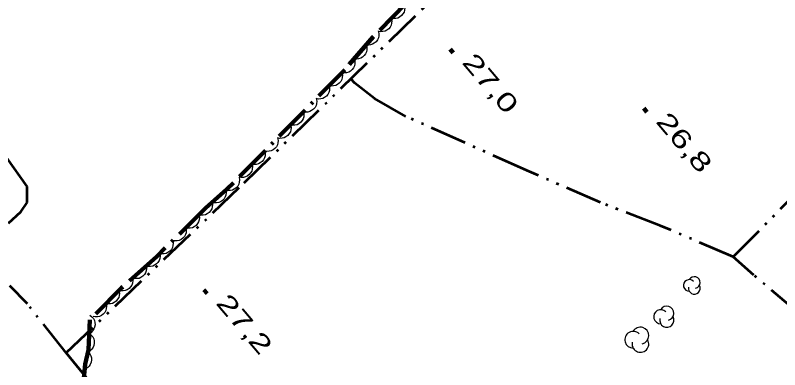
# Model space of a CAD drawing. Extents: x 386081 to 389416, y 5130568 to 5134082.
# Drawn here: x 388146 to 388270.9, y 5131665.7 to 5131723.7 of the extents above; entities that cross this region are included whole.
import ezdxf

# ---------------------------------------------------------------- set-up
doc = ezdxf.new("R2010")
doc.units = 0
doc.header["$LTSCALE"] = 1.2
doc.linetypes.add('DASH_DOUBLE_DOT', pattern=[9.2, 5, -1.2, 0.3, -1.2, 0.3, -1.2])
doc.linetypes.add('DOT_DASHED', pattern=[7.7, 5, -1.2, 0.3, -1.2])
for name, color, linetype, lineweight in [('3', 7, 'Continuous', 140), ('4', 7, 'DASH_DOUBLE_DOT', 53), ('44', 7, 'Continuous', 25)]:
    doc.layers.add(name, color=color, linetype=linetype, lineweight=lineweight)

msp = doc.modelspace()

# ---------------------------------------------------------------- linework, layer by layer
at = {"layer": '3'}
for p, q in [((388217.02, 5131718.17), (388217.53, 5131717.56)), ((388248.67, 5131708.5), (388249.18, 5131707.89)), ((388176.81, 5131678.8), (388177.32, 5131678.19))]:
    msp.add_line(p, q, dxfattribs=at)
at = {"layer": '4'}
for points in [[(388204.21, 5131610.66), (388196.86, 5131620.2), (388175.99, 5131644.63), (388165.41, 5131656.62), (388157.68, 5131664.34), (388154.31, 5131668.51), (388183.39, 5131696.3), (388212.47, 5131724.71), (388239.36, 5131750.62), (388265.61, 5131776.18), (388295.56, 5131805.65), (388308.21, 5131817.54), (388331.7, 5131840.05), (388348.88, 5131856.91), (388363.69, 5131871.25), (388382.99, 5131889.58), (388381.01, 5131890.93)], [(388263.29, 5131684.19), (388275.69, 5131696.8), (388295.26, 5131716.36), (388314.97, 5131735.57), (388331.43, 5131751.08), (388342.34, 5131761.72), (388346.88, 5131765.95), (388336.97, 5131780.58), (388318.64, 5131804.44), (388312.82, 5131811.58), (388308.21, 5131817.54)], [(388282.9, 5131667.63), (388274.12, 5131674.87), (388266.63, 5131681.22), (388263.29, 5131684.19), (388251.41, 5131689.3), (388241.59, 5131693.09), (388229.55, 5131698.34), (388209.82, 5131707.18), (388204.66, 5131710.12), (388201.44, 5131712.61), (388200.82, 5131713.34)], [(388144.86, 5131689.71), (388146.88, 5131691.59), (388147.91, 5131693.09), (388147.91, 5131695.74), (388144.6, 5131700.38)], [(388154.32, 5131668.51), (388147.98, 5131676.51), (388145.09, 5131679.45)]]:
    msp.add_lwpolyline(points, dxfattribs=at)
at = {"layer": '44', "linetype": 'DOT_DASHED', "lineweight": 90}
msp.add_lwpolyline([(388275.17, 5131788.24), (388266.86, 5131779.86), (388261.37, 5131774.72), (388253.26, 5131766.73), (388250.48, 5131764.17), (388246.51, 5131760.34), (388243.72, 5131757.88), (388240.74, 5131755.43), (388237.73, 5131752.74), (388224.13, 5131739.09), (388216.64, 5131732.25), (388209.73, 5131725.59), (388204.46, 5131720.2), (388199.81, 5131714.8), (388181.62, 5131696.3), (388180.56, 5131695.26), (388177.08, 5131692.16), (388169.1, 5131684.28), (388163.35, 5131679.13), (388158.15, 5131673.88), (388157.96, 5131668.98), (388157.4, 5131666.65), (388157.17, 5131664.33)], dxfattribs=at)
at = {"layer": '44'}
for points in [[(388209.53, 5131725.38), (388209.61, 5131724.97), (388209.57, 5131724.57), (388209.5, 5131724.25), (388209.33, 5131723.94), (388209.09, 5131723.66), (388208.78, 5131723.43), (388208.5, 5131723.27), (388208.16, 5131723.19), (388207.79, 5131723.17), (388207.43, 5131723.24)], [(388207.43, 5131723.24), (388207.51, 5131722.83), (388207.48, 5131722.42), (388207.4, 5131722.1), (388207.23, 5131721.8), (388207, 5131721.51), (388206.69, 5131721.29), (388206.4, 5131721.12), (388206.06, 5131721.05), (388205.69, 5131721.03), (388205.33, 5131721.09)], [(388205.28, 5131721.15), (388205.39, 5131720.74), (388205.37, 5131720.34), (388205.32, 5131720.01), (388205.17, 5131719.7), (388204.95, 5131719.4), (388204.65, 5131719.15), (388204.38, 5131718.97), (388204.04, 5131718.87), (388203.68, 5131718.83), (388203.32, 5131718.87)], [(388203.32, 5131718.87), (388203.43, 5131718.47), (388203.42, 5131718.06), (388203.36, 5131717.74), (388203.21, 5131717.42), (388202.99, 5131717.12), (388202.7, 5131716.88), (388202.43, 5131716.7), (388202.09, 5131716.6), (388201.72, 5131716.56), (388201.36, 5131716.6)], [(388201.36, 5131716.6), (388201.47, 5131716.2), (388201.46, 5131715.79), (388201.4, 5131715.46), (388201.25, 5131715.15), (388201.03, 5131714.85), (388200.74, 5131714.6), (388200.47, 5131714.42), (388200.13, 5131714.33), (388199.76, 5131714.29), (388199.4, 5131714.33)], [(388199.37, 5131714.36), (388199.46, 5131713.95), (388199.42, 5131713.54), (388199.34, 5131713.22), (388199.17, 5131712.91), (388198.93, 5131712.63), (388198.62, 5131712.4), (388198.34, 5131712.24), (388197.99, 5131712.17), (388197.62, 5131712.15), (388197.27, 5131712.22)], [(388197.27, 5131712.22), (388197.35, 5131711.81), (388197.31, 5131711.4), (388197.24, 5131711.08), (388197.06, 5131710.77), (388196.83, 5131710.49), (388196.52, 5131710.26), (388196.23, 5131710.1), (388195.89, 5131710.03), (388195.52, 5131710.01), (388195.17, 5131710.08)], [(388195.17, 5131710.08), (388195.25, 5131709.67), (388195.21, 5131709.26), (388195.13, 5131708.94), (388194.96, 5131708.64), (388194.73, 5131708.35), (388194.41, 5131708.13), (388194.13, 5131707.96), (388193.79, 5131707.89), (388193.42, 5131707.87), (388193.06, 5131707.94)], [(388193.06, 5131707.94), (388193.15, 5131707.53), (388193.11, 5131707.12), (388193.03, 5131706.8), (388192.86, 5131706.5), (388192.62, 5131706.21), (388192.31, 5131705.99), (388192.03, 5131705.82), (388191.68, 5131705.75), (388191.31, 5131705.73), (388190.96, 5131705.8)], [(388190.96, 5131705.8), (388191.04, 5131705.39), (388191, 5131704.98), (388190.93, 5131704.66), (388190.75, 5131704.36), (388190.52, 5131704.07), (388190.21, 5131703.85), (388189.92, 5131703.69), (388189.58, 5131703.61), (388189.21, 5131703.59), (388188.86, 5131703.66)], [(388188.86, 5131703.66), (388188.94, 5131703.25), (388188.9, 5131702.84), (388188.82, 5131702.52), (388188.65, 5131702.22), (388188.42, 5131701.93), (388188.1, 5131701.71), (388187.82, 5131701.55), (388187.48, 5131701.47), (388187.11, 5131701.46), (388186.75, 5131701.52)], [(388186.75, 5131701.52), (388186.84, 5131701.11), (388186.8, 5131700.71), (388186.72, 5131700.38), (388186.55, 5131700.08), (388186.31, 5131699.79), (388186, 5131699.57), (388185.72, 5131699.41), (388185.37, 5131699.33), (388185, 5131699.32), (388184.65, 5131699.38)], [(388184.65, 5131699.38), (388184.73, 5131698.97), (388184.69, 5131698.57), (388184.62, 5131698.24), (388184.44, 5131697.94), (388184.21, 5131697.65), (388183.9, 5131697.43), (388183.61, 5131697.27), (388183.27, 5131697.19), (388182.9, 5131697.18), (388182.55, 5131697.24)], [(388182.56, 5131697.22), (388182.64, 5131696.81), (388182.59, 5131696.41), (388182.51, 5131696.09), (388182.33, 5131695.79), (388182.09, 5131695.51), (388181.78, 5131695.29), (388181.49, 5131695.13), (388181.14, 5131695.06), (388180.77, 5131695.05), (388180.42, 5131695.12)], [(388180.41, 5131695.13), (388180.47, 5131694.72), (388180.4, 5131694.32), (388180.31, 5131694), (388180.11, 5131693.71), (388179.86, 5131693.44), (388179.54, 5131693.23), (388179.24, 5131693.09), (388178.89, 5131693.04), (388178.52, 5131693.05), (388178.17, 5131693.14)], [(388178.12, 5131693.19), (388178.2, 5131692.78), (388178.15, 5131692.38), (388178.08, 5131692.05), (388177.9, 5131691.75), (388177.66, 5131691.47), (388177.34, 5131691.25), (388177.06, 5131691.09), (388176.71, 5131691.02), (388176.34, 5131691.01), (388175.99, 5131691.08)], [(388175.99, 5131691.08), (388176.07, 5131690.67), (388176.02, 5131690.27), (388175.94, 5131689.95), (388175.76, 5131689.64), (388175.52, 5131689.36), (388175.21, 5131689.14), (388174.92, 5131688.98), (388174.58, 5131688.92), (388174.21, 5131688.9), (388173.85, 5131688.97)], [(388173.85, 5131688.97), (388173.93, 5131688.56), (388173.89, 5131688.16), (388173.81, 5131687.84), (388173.63, 5131687.54), (388173.39, 5131687.25), (388173.07, 5131687.03), (388172.79, 5131686.88), (388172.44, 5131686.81), (388172.07, 5131686.8), (388171.72, 5131686.87)], [(388171.72, 5131686.87), (388171.8, 5131686.46), (388171.75, 5131686.05), (388171.67, 5131685.73), (388171.49, 5131685.43), (388171.25, 5131685.15), (388170.94, 5131684.93), (388170.65, 5131684.77), (388170.31, 5131684.7), (388169.94, 5131684.69), (388169.58, 5131684.76)], [(388169.61, 5131684.73), (388169.66, 5131684.32), (388169.6, 5131683.92), (388169.5, 5131683.6), (388169.31, 5131683.31), (388169.06, 5131683.04), (388168.73, 5131682.84), (388168.44, 5131682.69), (388168.09, 5131682.64), (388167.72, 5131682.65), (388167.37, 5131682.73)], [(388167.37, 5131682.73), (388167.43, 5131682.32), (388167.36, 5131681.92), (388167.27, 5131681.6), (388167.08, 5131681.31), (388166.82, 5131681.04), (388166.5, 5131680.83), (388166.21, 5131680.69), (388165.86, 5131680.64), (388165.49, 5131680.64), (388165.14, 5131680.73)], [(388165.14, 5131680.73), (388165.19, 5131680.32), (388165.13, 5131679.92), (388165.03, 5131679.6), (388164.84, 5131679.31), (388164.59, 5131679.04), (388164.26, 5131678.83), (388163.97, 5131678.69), (388163.62, 5131678.64), (388163.25, 5131678.64), (388162.9, 5131678.73)], [(388162.93, 5131678.7), (388163.01, 5131678.29), (388162.97, 5131677.89), (388162.89, 5131677.57), (388162.72, 5131677.26), (388162.48, 5131676.98), (388162.17, 5131676.76), (388161.89, 5131676.59), (388161.54, 5131676.52), (388161.17, 5131676.51), (388160.82, 5131676.57)], [(388160.82, 5131676.57), (388160.9, 5131676.16), (388160.86, 5131675.76), (388160.78, 5131675.44), (388160.61, 5131675.13), (388160.37, 5131674.85), (388160.06, 5131674.62), (388159.77, 5131674.46), (388159.43, 5131674.39), (388159.06, 5131674.37), (388158.71, 5131674.44)], [(388158.18, 5131674.67), (388158.52, 5131674.42), (388158.76, 5131674.1), (388158.92, 5131673.81), (388159, 5131673.46), (388159.02, 5131673.1), (388158.94, 5131672.72), (388158.84, 5131672.41), (388158.63, 5131672.12), (388158.37, 5131671.86), (388158.06, 5131671.67)], [(388158.06, 5131671.67), (388158.4, 5131671.42), (388158.64, 5131671.1), (388158.81, 5131670.81), (388158.88, 5131670.47), (388158.9, 5131670.1), (388158.82, 5131669.72), (388158.72, 5131669.41), (388158.52, 5131669.13), (388158.25, 5131668.86), (388157.95, 5131668.67)], [(388157.89, 5131668.68), (388158.17, 5131668.37), (388158.35, 5131668.01), (388158.45, 5131667.69), (388158.45, 5131667.34), (388158.4, 5131666.98), (388158.25, 5131666.62), (388158.09, 5131666.34), (388157.83, 5131666.1), (388157.52, 5131665.89), (388157.19, 5131665.76)]]:
    msp.add_lwpolyline(points, dxfattribs=at)
for centre, radius, start, end in [((388256.929, 5131680.009), 0.954, 282.26917, 149.72626), ((388256.108, 5131679.532), 0.954, 44.11537, 269.80396), ((388256.929, 5131679.054), 0.954, 166.93686, 29.62122), ((388252.443, 5131674.995), 1.157, 282.26917, 149.72626), ((388251.448, 5131674.416), 1.157, 44.11537, 269.80396), ((388252.443, 5131673.838), 1.157, 166.93686, 29.62122), ((388246.944, 5131670.651), 1.369, 44.11537, 269.80396), ((388248.122, 5131671.336), 1.369, 282.26917, 149.72626), ((388248.122, 5131669.966), 1.369, 166.93686, 29.62122)]:
    msp.add_arc(centre, radius, start, end, dxfattribs=at)

# ---------------------------------------------------------------- texts
at = {"layer": '3', "width": 1.45}
for s, p in [('27,0   ', (388218.85, 5131715.95)), ('26,8   ', (388250.5, 5131706.28)), ('27,2   ', (388178.64, 5131676.58))]:
    msp.add_text(s, height=3, rotation=310.294, dxfattribs=at).set_placement(p)

doc.saveas('drawing.dxf')
